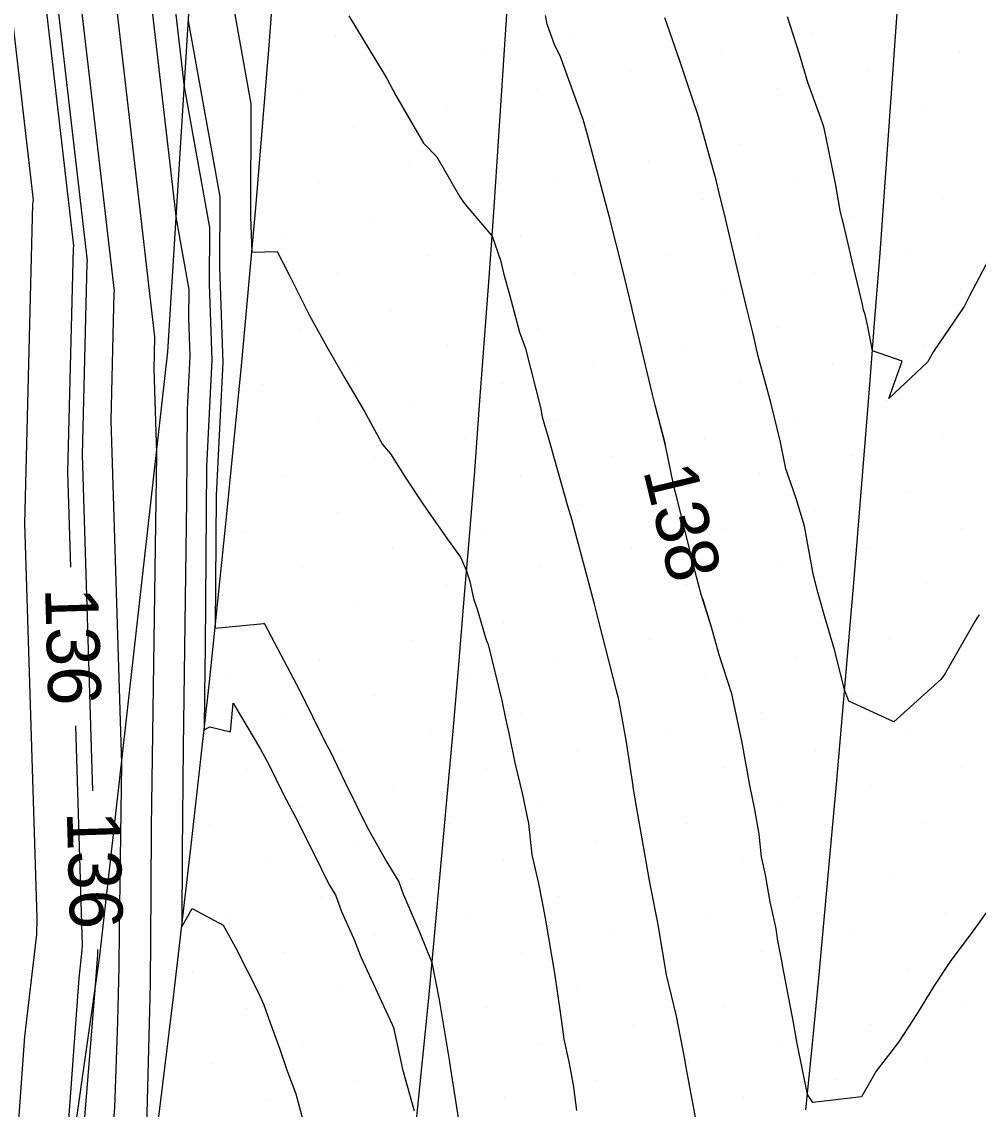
# Model space of a CAD drawing. Extents: x 2354170 to 2357230, y 866100 to 868290.
# Drawn here: x 2355317.68 to 2355353.82, y 866682.66 to 866723.76 of the extents above; entities that cross this region are included whole.
import ezdxf

# ---------------------------------------------------------------- set-up
doc = ezdxf.new("R2010")
doc.units = 0
for name, color, linetype in [('Default', 7, 'Continuous'), ('DTM Contours Minor', 7, 'Continuous'), ('DTM Contours Minor Text', 7, 'Continuous'), ('Exist DTM Breakline', 7, 'Continuous'), ('Exist DTM Scan Elevation Point', 7, 'Continuous'), ('Exist Roads EOP', 7, 'Continuous'), ('PH Exist DTM Breakline', 7, 'Continuous')]:
    doc.layers.add(name, color=color, linetype=linetype)

msp = doc.modelspace()

# ---------------------------------------------------------------- linework, layer by layer
at = {"layer": 'Default'}
for points in [[(2355319.531, 866703.142), (2355319.421, 866706.742), (2355319.627, 866715.191), (2355319.642, 866715.296), (2355317.686, 866732.184), (2355319.197, 866746.316), (2355319.69, 866753.255), (2355318.354, 866763.403), (2355318.019, 866774.259), (2355318.049, 866785.607), (2355318.635, 866801.132), (2355318.526, 866802.706), (2355318.518, 866802.818)], [(2355316.236, 866663.8), (2355317.798, 866685.403), (2355318.24, 866689.266), (2355318.255, 866689.894), (2355317.798, 866704.792), (2355318.093, 866716.87), (2355318.114, 866717.02), (2355316.489, 866731.051), (2355318.25, 866747.525), (2355318.678, 866753.545), (2355317.519, 866762.35)], [(2355321.276, 866735.582), (2355323.508, 866716.313), (2355323.986, 866713.639), (2355323.983, 866712.569), (2355324.033, 866711.122), (2355323.933, 866709.108), (2355323.903, 866705.684), (2355323.774, 866696.33), (2355323.742, 866692.392), (2355323.72, 866689.552), (2355324.115, 866690.251), (2355325.288, 866689.618), (2355325.739, 866688.796), (2355326.609, 866687.084), (2355326.83, 866686.608), (2355327.062, 866685.919), (2355327.423, 866684.925), (2355327.683, 866684.176), (2355328.028, 866683.244), (2355328.343, 866682.073)], [(2355320.079, 866734.449), (2355322.698, 866711.847), (2355322.696, 866711.832), (2355322.667, 866710.642), (2355322.765, 866707.438), (2355322.571, 866693.323), (2355322.551, 866690.888), (2355322.523, 866687.386), (2355322.39, 866682.008)], [(2355318.882, 866733.317), (2355321.17, 866713.572), (2355321.161, 866713.512), (2355321.044, 866708.692), (2355321.442, 866695.716), (2355321.367, 866690.316), (2355321.36, 866689.384), (2355321.349, 866688.044), (2355321.298, 866685.987), (2355321.181, 866682.717), (2355320.209, 866670.693)], [(2355324.43, 866731.285), (2355326.327, 866720.655), (2355326.318, 866716.401), (2355326.365, 866715.046), (2355327.33, 866715.08), (2355327.783, 866714.196), (2355328.544, 866712.663), (2355329.206, 866711.479), (2355329.928, 866710.224), (2355330.628, 866709.03), (2355331.309, 866707.78), (2355331.605, 866707.425), (2355332.192, 866706.505), (2355332.827, 866705.544), (2355333.791, 866704.162), (2355334.257, 866703.528), (2355334.487, 866703.009), (2355334.612, 866702.601), (2355334.745, 866701.968), (2355334.882, 866701.555), (2355335.224, 866700.404), (2355335.302, 866700.223), (2355335.823, 866698.108), (2355335.951, 866697.422), (2355336.084, 866696.874), (2355336.306, 866695.754), (2355336.587, 866694.605), (2355336.822, 866693.459), (2355336.956, 866692.278), (2355337.207, 866691.197), (2355337.335, 866690.552), (2355337.454, 866689.883), (2355337.802, 866687.806), (2355338.039, 866686.236), (2355338.161, 866685.308), (2355338.351, 866684.445), (2355338.518, 866683.576), (2355338.64, 866682.614)], [(2355323.969, 866723.799), (2355325.156, 866717.147), (2355325.151, 866714.485), (2355325.275, 866710.885), (2355325.025, 866705.873), (2355324.981, 866700.846), (2355326.824, 866701.014), (2355326.841, 866701.027), (2355326.866, 866700.98), (2355328.169, 866698.504), (2355329.137, 866696.536), (2355329.351, 866696.142), (2355329.459, 866695.923), (2355329.881, 866695.035), (2355330.735, 866693.32), (2355331.472, 866691.994), (2355331.926, 866691.254), (2355332.081, 866690.823), (2355332.715, 866689.326), (2355333.178, 866688.205), (2355333.449, 866686.793), (2355333.838, 866684.449), (2355333.842, 866684.428), (2355333.842, 866684.423), (2355334.363, 866681.05)], [(2355330.039, 866723.985), (2355331.124, 866722.2), (2355331.361, 866721.808), (2355331.467, 866721.611), (2355331.814, 866720.975), (2355332.854, 866719.177), (2355333.356, 866718.656), (2355334.232, 866717.147), (2355334.369, 866716.936), (2355334.511, 866716.76), (2355335.451, 866715.655), (2355335.764, 866714.75), (2355335.885, 866714.259), (2355336.122, 866713.398), (2355336.488, 866712.03), (2355336.709, 866711.412), (2355337.295, 866709.125), (2355337.343, 866708.821), (2355337.544, 866708.143), (2355338.299, 866705.463), (2355338.445, 866704.974), (2355339.288, 866701.811), (2355339.306, 866701.745), (2355339.461, 866701.145), (2355340.143, 866698.479), (2355340.211, 866698.203), (2355340.504, 866696.609), (2355340.762, 866694.883), (2355340.767, 866694.858), (2355340.77, 866694.835), (2355340.911, 866694.026), (2355341.36, 866691.447), (2355341.374, 866691.374), (2355341.386, 866691.296), (2355341.715, 866689.639), (2355341.974, 866688.043), (2355342.032, 866687.741), (2355342.408, 866686.172), (2355342.717, 866684.554), (2355342.758, 866684.308), (2355343.355, 866681.135)], [(2355341.997, 866707.78), (2355341.607, 866709.27), (2355341.52, 866709.622), (2355340.759, 866712.828), (2355340.744, 866712.894), (2355340.73, 866712.958), (2355340.346, 866714.517), (2355339.917, 866716.26), (2355339.898, 866716.33), (2355339.876, 866716.41), (2355339.052, 866719.484), (2355338.888, 866720.061), (2355338.028, 866722.467), (2355337.823, 866722.856), (2355337.534, 866723.663), (2355337.473, 866723.995)], [(2355353.854, 866701.339), (2355353.773, 866701.22), (2355353.693, 866701.099), (2355352.579, 866699.152), (2355352.524, 866699.057), (2355352.52, 866699.052), (2355352.517, 866699.046), (2355352.412, 866698.899), (2355350.631, 866697.304), (2355348.924, 866698.077), (2355348.772, 866698.512), (2355348.402, 866699.98), (2355348.012, 866701.311), (2355347.765, 866702.197), (2355347.588, 866702.898), (2355347.251, 866704.691), (2355346.943, 866705.739), (2355346.544, 866706.859), (2355346.354, 866707.866), (2355345.982, 866709.373), (2355345.506, 866711.116), (2355345.307, 866712.02), (2355345.065, 866712.977), (2355344.714, 866714.45), (2355344.213, 866716.538), (2355344.06, 866717.178), (2355343.915, 866717.772), (2355343.246, 866720.175), (2355343.001, 866720.921), (2355342.545, 866722.282), (2355341.98, 866723.91)], [(2355354.583, 866715.478), (2355353.489, 866713.399), (2355353.283, 866713.001), (2355352.128, 866711.301), (2355351.909, 866710.891), (2355350.446, 866709.521), (2355350.945, 866710.927), (2355349.821, 866711.324), (2355349.644, 866712.238), (2355349.552, 866712.7), (2355349.49, 866712.871), (2355349.446, 866713.076), (2355349.06, 866714.714), (2355348.751, 866716.02), (2355348.674, 866716.313), (2355348.608, 866716.628), (2355348.43, 866717.647), (2355348.054, 866719.498), (2355347.99, 866719.782), (2355347.876, 866720.11), (2355347.376, 866721.461), (2355347.063, 866722.53), (2355346.609, 866723.946)], [(2355354.292, 866690.331), (2355353.59, 866689.351), (2355352.79, 866688.287), (2355352.139, 866687.314), (2355351.509, 866686.278), (2355350.803, 866685.2), (2355349.962, 866684.103), (2355349.411, 866683.123), (2355347.57, 866682.911), (2355347.369, 866683.22), (2355346.978, 866685.146), (2355346.835, 866685.939), (2355346.419, 866688.1), (2355346.396, 866688.268), (2355346.249, 866689.018), (2355346.178, 866689.477), (2355345.96, 866690.504), (2355345.785, 866691.517), (2355345.625, 866692.202), (2355345.546, 866693.053), (2355345.372, 866693.992), (2355345.184, 866694.913), (2355344.887, 866696.588), (2355344.51, 866698.356), (2355344.035, 866699.83), (2355343.737, 866700.876), (2355343.407, 866701.95)], [(2355320.167, 866650.162), (2355319.525, 866651.157), (2355319.45, 866652.954), (2355318.935, 866652.48), (2355318.488, 866655.679), (2355318.378, 866659.658), (2355318.404, 866662.828), (2355318.092, 866664.358), (2355318.142, 866665.565), (2355319.157, 866678.118), (2355319.844, 866687.612), (2355319.965, 866688.677), (2355319.97, 866688.85), (2355319.715, 866697.145)]]:
    msp.add_lwpolyline(points, dxfattribs=at)
at = {"layer": 'DTM Contours Minor'}
for points in [[(2355314.895, 866894.262), (2355315.108, 866889.287), (2355315.119, 866889.115), (2355315.275, 866880.887), (2355316.318, 866861.986), (2355316.331, 866861.214), (2355316.625, 866853.034), (2355317.045, 866833.773), (2355317.084, 866832.738), (2355317.087, 866832.683), (2355318.083, 866812.944), (2355318.793, 866802.704), (2355318.908, 866801.047), (2355318.342, 866786.065), (2355318.311, 866774.182), (2355318.633, 866763.754), (2355320.027, 866753.158), (2355319.512, 866745.912), (2355318.085, 866732.561), (2355320.151, 866714.721), (2355320.138, 866714.631), (2355319.962, 866707.392), (2355320.351, 866694.691)], [(2355322.074, 866736.337), (2355323.816, 866721.304), (2355324.766, 866715.978), (2355324.762, 866713.847), (2355324.861, 866710.964), (2355324.661, 866706.951), (2355324.601, 866700.132), (2355324.577, 866698.335), (2355324.566, 866696.998), (2355324.778, 866697.115), (2355325.569, 866696.928), (2355325.666, 866698.012), (2355326.693, 866696.273), (2355327.022, 866695.667), (2355327.558, 866694.583), (2355328.008, 866693.729), (2355328.681, 866692.397), (2355329.296, 866691.146), (2355329.529, 866690.766), (2355329.757, 866690.131), (2355330.226, 866689.104), (2355330.487, 866688.414), (2355331.677, 866685.863), (2355331.721, 866685.75), (2355332.062, 866684.169), (2355332.51, 866682.605)], [(2355354.292, 866690.331), (2355353.59, 866689.351), (2355352.79, 866688.287), (2355352.139, 866687.314), (2355351.509, 866686.278), (2355350.803, 866685.2), (2355349.962, 866684.103), (2355349.411, 866683.123), (2355347.57, 866682.911), (2355347.369, 866683.22), (2355346.978, 866685.146), (2355346.835, 866685.939), (2355346.419, 866688.1), (2355346.396, 866688.268), (2355346.249, 866689.018), (2355346.178, 866689.477), (2355345.96, 866690.504), (2355345.785, 866691.517), (2355345.625, 866692.202), (2355345.546, 866693.053), (2355345.372, 866693.992), (2355345.184, 866694.913), (2355344.887, 866696.588), (2355344.51, 866698.356), (2355344.035, 866699.83), (2355343.737, 866700.876), (2355343.356, 866702.117), (2355343.118, 866702.975), (2355342.437, 866705.723), (2355342.364, 866706.008), (2355342.302, 866706.273), (2355342.008, 866707.74), (2355341.607, 866709.27), (2355341.52, 866709.622), (2355340.759, 866712.828), (2355340.744, 866712.894), (2355340.73, 866712.958), (2355340.346, 866714.517), (2355339.917, 866716.26), (2355339.898, 866716.33), (2355339.876, 866716.41), (2355339.052, 866719.484), (2355338.888, 866720.061), (2355338.028, 866722.467), (2355337.823, 866722.856), (2355337.534, 866723.663), (2355337.473, 866723.995)], [(2355320.535, 866688.694), (2355320.541, 866688.502), (2355320.541, 866688.48), (2355320.526, 866688.348), (2355320.441, 866687.174), (2355318.831, 866667.274), (2355318.753, 866665.362), (2355319.246, 866662.936), (2355319.206, 866657.911), (2355319.24, 866656.688), (2355319.377, 866655.704), (2355319.783, 866656.078), (2355320.681, 866655.47), (2355320.967, 866653.98), (2355321.18, 866651.693), (2355321.372, 866650.714), (2355321.738, 866649.49)]]:
    msp.add_lwpolyline(points, dxfattribs=at)
at = {"layer": 'Exist DTM Breakline'}
for points in [[(2355347.311, 866682.641), (2355347.56, 866685.128), (2355347.791, 866687.618), (2355348.022, 866690.107), (2355348.253, 866692.596), (2355348.482, 866695.086), (2355348.693, 866697.577), (2355348.904, 866700.068), (2355349.115, 866702.559), (2355349.325, 866705.05), (2355349.522, 866707.542), (2355349.719, 866710.035), (2355349.916, 866712.527), (2355350.111, 866715.019), (2355350.289, 866717.513), (2355350.467, 866720.006), (2355350.646, 866722.5), (2355350.822, 866724.994)], [(2355332.553, 866681.881), (2355332.809, 866684.368), (2355333.053, 866686.856), (2355333.283, 866689.345), (2355333.513, 866691.834), (2355333.744, 866694.324), (2355333.964, 866696.814), (2355334.174, 866699.305), (2355334.384, 866701.796), (2355334.594, 866704.287), (2355334.792, 866706.779), (2355334.979, 866709.272), (2355335.166, 866711.766), (2355335.353, 866714.259), (2355335.528, 866716.752), (2355335.69, 866719.247), (2355335.853, 866721.742), (2355336.016, 866724.236)]]:
    msp.add_lwpolyline(points, dxfattribs=at)
at = {"layer": 'Exist DTM Scan Elevation Point'}
for p, q in [((2355329.548, 866723.243), (2355329.548, 866723.243)), ((2355338.562, 866723.274), (2355338.562, 866723.274)), ((2355347.576, 866723.306), (2355347.576, 866723.306)), ((2355335.098, 866722.569), (2355335.098, 866722.569)), ((2355344.112, 866722.601), (2355344.112, 866722.601)), ((2355353.125, 866722.632), (2355353.125, 866722.632)), ((2355331.633, 866721.863), (2355331.633, 866721.863)), ((2355340.647, 866721.895), (2355340.647, 866721.895)), ((2355349.661, 866721.927), (2355349.661, 866721.927)), ((2355328.169, 866721.158), (2355328.169, 866721.158)), ((2355337.183, 866721.189), (2355337.183, 866721.189)), ((2355346.197, 866721.221), (2355346.197, 866721.221)), ((2355342.732, 866720.516), (2355342.732, 866720.516)), ((2355351.746, 866720.547), (2355351.746, 866720.547)), ((2355333.718, 866720.484), (2355333.718, 866720.484)), ((2355330.254, 866719.778), (2355330.254, 866719.778)), ((2355339.268, 866719.81), (2355339.268, 866719.81)), ((2355348.282, 866719.842), (2355348.282, 866719.842)), ((2355335.803, 866719.104), (2355335.803, 866719.104)), ((2355344.817, 866719.136), (2355344.817, 866719.136)), ((2355332.339, 866718.399), (2355332.339, 866718.399)), ((2355341.353, 866718.431), (2355341.353, 866718.431)), ((2355328.875, 866717.693), (2355328.875, 866717.693)), ((2355337.888, 866717.725), (2355337.888, 866717.725)), ((2355346.902, 866717.757), (2355346.902, 866717.757)), ((2355334.424, 866717.019), (2355334.424, 866717.019)), ((2355343.438, 866717.051), (2355343.438, 866717.051)), ((2355352.452, 866717.083), (2355352.452, 866717.083)), ((2355330.96, 866716.314), (2355330.96, 866716.314)), ((2355339.973, 866716.346), (2355339.973, 866716.346)), ((2355348.987, 866716.377), (2355348.987, 866716.377)), ((2355327.495, 866715.608), (2355327.495, 866715.608)), ((2355336.509, 866715.64), (2355336.509, 866715.64)), ((2355345.523, 866715.672), (2355345.523, 866715.672)), ((2355333.045, 866714.934), (2355333.045, 866714.934)), ((2355342.058, 866714.966), (2355342.058, 866714.966)), ((2355351.072, 866714.998), (2355351.072, 866714.998)), ((2355329.58, 866714.229), (2355329.58, 866714.229)), ((2355338.594, 866714.261), (2355338.594, 866714.261)), ((2355347.608, 866714.292), (2355347.608, 866714.292)), ((2355335.13, 866713.555), (2355335.13, 866713.555)), ((2355344.143, 866713.587), (2355344.143, 866713.587)), ((2355353.157, 866713.618), (2355353.157, 866713.618)), ((2355331.665, 866712.849), (2355331.665, 866712.849)), ((2355340.679, 866712.881), (2355340.679, 866712.881)), ((2355349.693, 866712.913), (2355349.693, 866712.913)), ((2355328.201, 866712.144), (2355328.201, 866712.144)), ((2355337.215, 866712.176), (2355337.215, 866712.176)), ((2355346.228, 866712.207), (2355346.228, 866712.207)), ((2355333.75, 866711.47), (2355333.75, 866711.47)), ((2355342.764, 866711.502), (2355342.764, 866711.502)), ((2355351.778, 866711.533), (2355351.778, 866711.533)), ((2355330.286, 866710.765), (2355330.286, 866710.765)), ((2355339.299, 866710.796), (2355339.299, 866710.796)), ((2355348.313, 866710.828), (2355348.313, 866710.828)), ((2355326.821, 866710.059), (2355326.821, 866710.059)), ((2355335.835, 866710.091), (2355335.835, 866710.091)), ((2355344.849, 866710.122), (2355344.849, 866710.122)), ((2355341.384, 866709.417), (2355341.384, 866709.417)), ((2355350.398, 866709.448), (2355350.398, 866709.448)), ((2355332.371, 866709.385), (2355332.371, 866709.385)), ((2355328.906, 866708.68), (2355328.906, 866708.68)), ((2355337.92, 866708.711), (2355337.92, 866708.711)), ((2355346.934, 866708.743), (2355346.934, 866708.743)), ((2355334.456, 866708.006), (2355334.456, 866708.006)), ((2355343.469, 866708.037), (2355343.469, 866708.037)), ((2355352.483, 866708.069), (2355352.483, 866708.069)), ((2355349.019, 866707.363), (2355349.019, 866707.363)), ((2355330.991, 866707.3), (2355330.991, 866707.3)), ((2355340.005, 866707.332), (2355340.005, 866707.332)), ((2355327.527, 866706.595), (2355327.527, 866706.595)), ((2355336.541, 866706.626), (2355336.541, 866706.626)), ((2355345.554, 866706.658), (2355345.554, 866706.658)), ((2355333.076, 866705.921), (2355333.076, 866705.921)), ((2355342.09, 866705.952), (2355342.09, 866705.952)), ((2355351.104, 866705.984), (2355351.104, 866705.984)), ((2355329.612, 866705.215), (2355329.612, 866705.215)), ((2355338.626, 866705.247), (2355338.626, 866705.247)), ((2355347.639, 866705.278), (2355347.639, 866705.278)), ((2355326.147, 866704.51), (2355326.147, 866704.51)), ((2355335.161, 866704.541), (2355335.161, 866704.541)), ((2355344.175, 866704.573), (2355344.175, 866704.573)), ((2355353.189, 866704.605), (2355353.189, 866704.605)), ((2355331.697, 866703.836), (2355331.697, 866703.836)), ((2355340.711, 866703.867), (2355340.711, 866703.867)), ((2355349.724, 866703.899), (2355349.724, 866703.899)), ((2355328.232, 866703.13), (2355328.232, 866703.13)), ((2355337.246, 866703.162), (2355337.246, 866703.162)), ((2355346.26, 866703.193), (2355346.26, 866703.193)), ((2355333.782, 866702.456), (2355333.782, 866702.456)), ((2355342.796, 866702.488), (2355342.796, 866702.488)), ((2355351.809, 866702.52), (2355351.809, 866702.52)), ((2355330.317, 866701.751), (2355330.317, 866701.751)), ((2355339.331, 866701.782), (2355339.331, 866701.782)), ((2355348.345, 866701.814), (2355348.345, 866701.814)), ((2355326.853, 866701.045), (2355326.853, 866701.045)), ((2355335.867, 866701.077), (2355335.867, 866701.077)), ((2355344.881, 866701.108), (2355344.881, 866701.108)), ((2355332.402, 866700.371), (2355332.402, 866700.371)), ((2355341.416, 866700.403), (2355341.416, 866700.403)), ((2355350.43, 866700.435), (2355350.43, 866700.435)), ((2355328.938, 866699.666), (2355328.938, 866699.666)), ((2355337.952, 866699.697), (2355337.952, 866699.697)), ((2355346.966, 866699.729), (2355346.966, 866699.729)), ((2355325.473, 866698.96), (2355325.473, 866698.96)), ((2355334.487, 866698.992), (2355334.487, 866698.992)), ((2355343.501, 866699.023), (2355343.501, 866699.023)), ((2355352.515, 866699.055), (2355352.515, 866699.055)), ((2355340.037, 866698.318), (2355340.037, 866698.318)), ((2355349.051, 866698.35), (2355349.051, 866698.35)), ((2355331.023, 866698.286), (2355331.023, 866698.286)), ((2355327.558, 866697.581), (2355327.558, 866697.581)), ((2355336.572, 866697.612), (2355336.572, 866697.612)), ((2355345.586, 866697.644), (2355345.586, 866697.644)), ((2355333.108, 866696.907), (2355333.108, 866696.907)), ((2355342.122, 866696.939), (2355342.122, 866696.939)), ((2355351.136, 866696.97), (2355351.136, 866696.97)), ((2355347.671, 866696.265), (2355347.671, 866696.265)), ((2355329.643, 866696.201), (2355329.643, 866696.201)), ((2355338.657, 866696.233), (2355338.657, 866696.233)), ((2355326.179, 866695.496), (2355326.179, 866695.496)), ((2355335.193, 866695.527), (2355335.193, 866695.527)), ((2355344.207, 866695.559), (2355344.207, 866695.559)), ((2355353.221, 866695.591), (2355353.221, 866695.591)), ((2355331.728, 866694.822), (2355331.728, 866694.822)), ((2355340.742, 866694.854), (2355340.742, 866694.854)), ((2355349.756, 866694.885), (2355349.756, 866694.885)), ((2355328.264, 866694.116), (2355328.264, 866694.116)), ((2355337.278, 866694.148), (2355337.278, 866694.148)), ((2355346.292, 866694.18), (2355346.292, 866694.18)), ((2355324.8, 866693.411), (2355324.8, 866693.411)), ((2355333.813, 866693.442), (2355333.813, 866693.442)), ((2355342.827, 866693.474), (2355342.827, 866693.474)), ((2355351.841, 866693.506), (2355351.841, 866693.506)), ((2355330.349, 866692.737), (2355330.349, 866692.737)), ((2355339.363, 866692.769), (2355339.363, 866692.769)), ((2355348.377, 866692.8), (2355348.377, 866692.8)), ((2355326.885, 866692.031), (2355326.885, 866692.031)), ((2355335.898, 866692.063), (2355335.898, 866692.063)), ((2355344.912, 866692.095), (2355344.912, 866692.095)), ((2355332.434, 866691.357), (2355332.434, 866691.357)), ((2355341.448, 866691.389), (2355341.448, 866691.389)), ((2355350.462, 866691.421), (2355350.462, 866691.421)), ((2355328.97, 866690.652), (2355328.97, 866690.652)), ((2355337.983, 866690.684), (2355337.983, 866690.684)), ((2355346.997, 866690.715), (2355346.997, 866690.715)), ((2355325.505, 866689.946), (2355325.505, 866689.946)), ((2355334.519, 866689.978), (2355334.519, 866689.978)), ((2355343.533, 866690.01), (2355343.533, 866690.01)), ((2355352.547, 866690.041), (2355352.547, 866690.041)), ((2355331.055, 866689.272), (2355331.055, 866689.272)), ((2355340.068, 866689.304), (2355340.068, 866689.304)), ((2355349.082, 866689.336), (2355349.082, 866689.336)), ((2355327.59, 866688.567), (2355327.59, 866688.567)), ((2355336.604, 866688.599), (2355336.604, 866688.599)), ((2355345.618, 866688.63), (2355345.618, 866688.63)), ((2355324.126, 866687.861), (2355324.126, 866687.861)), ((2355342.153, 866687.925), (2355342.153, 866687.925)), ((2355351.167, 866687.956), (2355351.167, 866687.956)), ((2355338.689, 866687.219), (2355338.689, 866687.219)), ((2355347.703, 866687.251), (2355347.703, 866687.251)), ((2355329.675, 866687.187), (2355329.675, 866687.187)), ((2355326.211, 866686.482), (2355326.211, 866686.482)), ((2355335.225, 866686.514), (2355335.225, 866686.514)), ((2355344.238, 866686.545), (2355344.238, 866686.545)), ((2355353.252, 866686.577), (2355353.252, 866686.577)), ((2355331.76, 866685.808), (2355331.76, 866685.808)), ((2355340.774, 866685.84), (2355340.774, 866685.84)), ((2355349.788, 866685.871), (2355349.788, 866685.871)), ((2355346.323, 866685.166), (2355346.323, 866685.166)), ((2355328.296, 866685.102), (2355328.296, 866685.102)), ((2355337.31, 866685.134), (2355337.31, 866685.134)), ((2355324.831, 866684.397), (2355324.831, 866684.397)), ((2355333.845, 866684.429), (2355333.845, 866684.429)), ((2355342.859, 866684.46), (2355342.859, 866684.46)), ((2355351.873, 866684.492), (2355351.873, 866684.492)), ((2355330.381, 866683.723), (2355330.381, 866683.723)), ((2355339.395, 866683.755), (2355339.395, 866683.755)), ((2355348.408, 866683.786), (2355348.408, 866683.786)), ((2355326.916, 866683.017), (2355326.916, 866683.017)), ((2355335.93, 866683.049), (2355335.93, 866683.049)), ((2355344.944, 866683.081), (2355344.944, 866683.081))]:
    msp.add_line(p, q, dxfattribs=at)
at = {"layer": 'Exist Roads EOP'}
msp.add_lwpolyline([(2355317.935, 866645.248), (2355318.758, 866651.191), (2355319.573, 866657.136), (2355320.377, 866663.082), (2355321.166, 866669.029), (2355321.936, 866674.98), (2355322.685, 866680.933), (2355323.409, 866686.889), (2355324.104, 866692.849), (2355324.767, 866698.812), (2355325.394, 866704.779), (2355325.978, 866710.751), (2355326.516, 866716.726), (2355327.012, 866722.706), (2355327.468, 866728.688)], dxfattribs=at)
at = {"layer": 'PH Exist DTM Breakline'}
msp.add_lwpolyline([(2355207.55, 866297.674), (2355225.072, 866335.019), (2355245.676, 866379.995), (2355260.219, 866424.767), (2355273.655, 866466.636), (2355281.785, 866490.339), (2355287.686, 866512.788), (2355295.16, 866540.197), (2355297.267, 866553.045), (2355302.012, 866582.828), (2355309.884, 866621.381), (2355316.964, 866662.644), (2355320.622, 866688.452), (2355323.199, 866711.282), (2355324.906, 866739.018), (2355325.362, 866751.624)], dxfattribs=at)

# ---------------------------------------------------------------- texts
at = {"layer": 'Default'}
for s, rotation, p in [('138', 283.5946, (2355341.153, 866706.8)), ('136', 271.7572, (2355318.555, 866702.356))]:
    msp.add_text(s, height=2, rotation=rotation, dxfattribs=at).set_placement(p)
at = {"layer": 'DTM Contours Minor Text'}
msp.add_text('136', height=2, rotation=271.7572, dxfattribs=at).set_placement((2355319.375, 866693.905))

doc.saveas('drawing.dxf')
